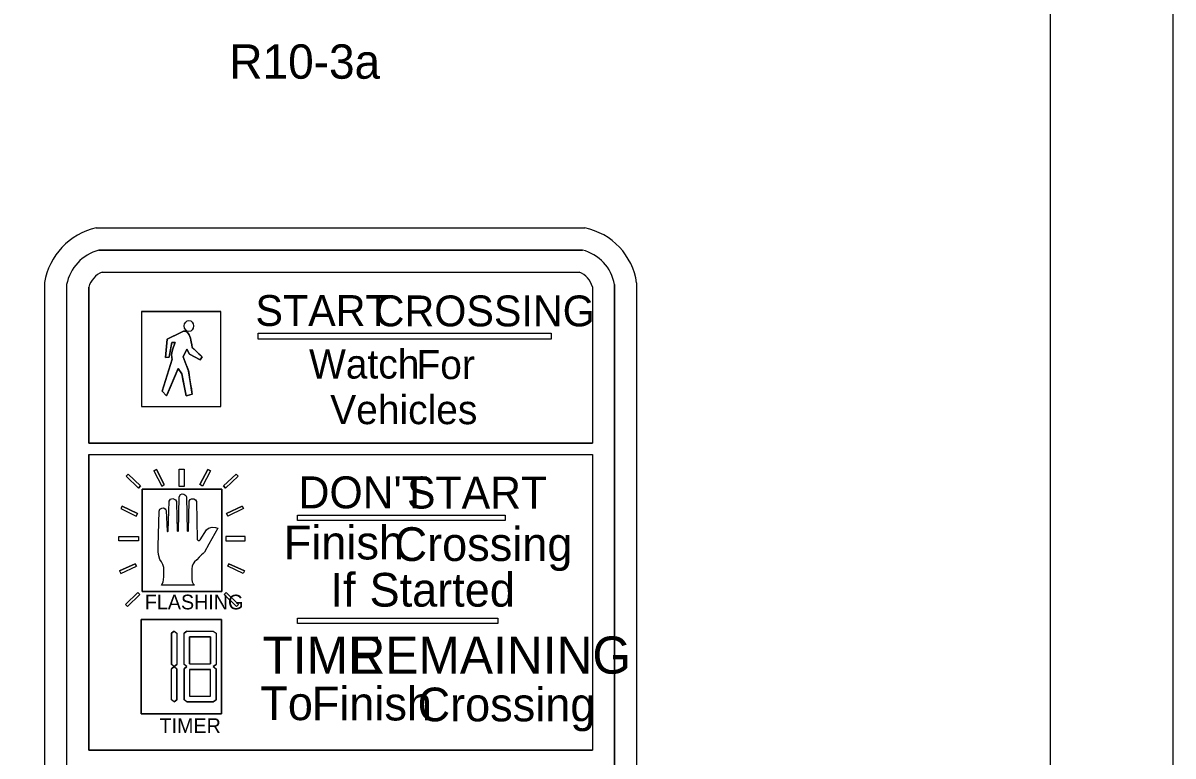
# Model space of a CAD drawing. Extents: x 1896459 to 1901611, y 1616229 to 1617416.
# Drawn here: x 1897924.9 to 1898159.1, y 1616969.5 to 1617118.8 of the extents above; entities that cross this region are included whole.
import ezdxf

# ---------------------------------------------------------------- set-up
doc = ezdxf.new("R2010")
doc.units = 0
for name, color, linetype in [('Level 8', 7, 'Continuous'), ('ROW_PR_Notes', 7, 'Continuous'), ('Sheets_General Details', 7, 'Continuous'), ('Signals_EX_Above Ground', 7, 'Continuous')]:
    doc.layers.add(name, color=color, linetype=linetype)

msp = doc.modelspace()

# ---------------------------------------------------------------- linework, layer by layer
at = {"layer": 'ROW_PR_Notes'}
for p, q in [((1897939.77, 1617077.06), (1898039.28, 1617077.06)), ((1897940.32, 1617072.56), (1898038.79, 1617072.56)), ((1898038.79, 1617072.56), (1897940.32, 1617072.56)), ((1897941.02, 1617068.06), (1898038.14, 1617068.06)), ((1897941.02, 1617068.06), (1898038.14, 1617068.06)), ((1897929.26, 1617065.93), (1897929.26, 1616886.19)), ((1897933.76, 1617065.54), (1897933.76, 1616886.41)), ((1897933.76, 1617065.54), (1897933.76, 1616886.41)), ((1897938.26, 1617065.02), (1897938.26, 1617033.2)), ((1897938.26, 1617033.2), (1897938.26, 1617065.02)), ((1898040.84, 1617065.07), (1898040.84, 1617033.2)), ((1898040.84, 1617065.07), (1898040.84, 1617033.2)), ((1898045.34, 1617065.54), (1898045.34, 1616886.41)), ((1898045.34, 1616886.41), (1898045.34, 1617065.54)), ((1898049.84, 1617065.89), (1898049.84, 1616886.08)), ((1897949, 1617060.03), (1897965.15, 1617060.03)), ((1897965.15, 1617060.03), (1897949, 1617060.03)), ((1897957.17, 1617055.86), (1897957.56, 1617056.04)), ((1897953.93, 1617050.65), (1897954.24, 1617054.42)), ((1897959.06, 1617054.21), (1897959.15, 1617053.85)), ((1897959.15, 1617053.85), (1897959.28, 1617053.23)), ((1897959.28, 1617053.23), (1897959.35, 1617052.74)), ((1897953.22, 1617043.83), (1897955.28, 1617050.34)), ((1897954.66, 1617050.73), (1897953.93, 1617050.65)), ((1897955.15, 1617051.24), (1897955.21, 1617051.65)), ((1897955.21, 1617051.65), (1897955.34, 1617052.22)), ((1897955.28, 1617050.34), (1897955.21, 1617050.62)), ((1897958.76, 1617051.34), (1897958.27, 1617052.39)), ((1897960.99, 1617050.19), (1897958.76, 1617051.34)), ((1897961.39, 1617050.84), (1897960.99, 1617050.19)), ((1897957.6, 1617045.39), (1897957.22, 1617047.33)), ((1897954.11, 1617042.89), (1897953.22, 1617043.83)), ((1897938.26, 1617033.2), (1898040.84, 1617033.2)), ((1898040.84, 1617033.2), (1897938.26, 1617033.2)), ((1897938.26, 1617030.88), (1898040.84, 1617030.88)), ((1897938.26, 1617030.88), (1897938.26, 1616970.64)), ((1897938.26, 1616970.64), (1897938.26, 1617030.88)), ((1897938.26, 1617030.88), (1898040.84, 1617030.88)), ((1898040.84, 1617030.88), (1898040.84, 1616970.64)), ((1898040.84, 1617030.88), (1898040.84, 1616970.64)), ((1897946.27, 1617026.91), (1897945.87, 1617026.48)), ((1897946.27, 1617026.91), (1897945.87, 1617026.48)), ((1897946.27, 1617026.91), (1897948.81, 1617024.5)), ((1897948.81, 1617024.5), (1897946.27, 1617026.91)), ((1897951.52, 1617027.6), (1897952.04, 1617027.87)), ((1897952.04, 1617027.87), (1897951.52, 1617027.6)), ((1897951.52, 1617027.6), (1897953.13, 1617024.49)), ((1897951.52, 1617027.6), (1897953.13, 1617024.49)), ((1897952.04, 1617027.87), (1897953.66, 1617024.77)), ((1897953.66, 1617024.77), (1897952.04, 1617027.87)), ((1897962.5, 1617027.87), (1897960.89, 1617024.77)), ((1897960.89, 1617024.77), (1897962.5, 1617027.87)), ((1897963.03, 1617027.6), (1897961.41, 1617024.49)), ((1897963.03, 1617027.6), (1897961.41, 1617024.49)), ((1897963.03, 1617027.6), (1897962.5, 1617027.87)), ((1897962.5, 1617027.87), (1897963.03, 1617027.6)), ((1897968.27, 1617026.91), (1897965.73, 1617024.5)), ((1897965.73, 1617024.5), (1897968.27, 1617026.91)), ((1897968.27, 1617026.91), (1897968.68, 1617026.48)), ((1897968.27, 1617026.91), (1897968.68, 1617026.48)), ((1897945.87, 1617026.48), (1897948.41, 1617024.07)), ((1897945.87, 1617026.48), (1897948.41, 1617024.07)), ((1897948.81, 1617024.5), (1897948.41, 1617024.07)), ((1897948.41, 1617024.07), (1897948.81, 1617024.5)), ((1897953.13, 1617024.49), (1897953.66, 1617024.77)), ((1897953.13, 1617024.49), (1897953.66, 1617024.77)), ((1897961.41, 1617024.49), (1897960.89, 1617024.77)), ((1897961.41, 1617024.49), (1897960.89, 1617024.77)), ((1897965.73, 1617024.5), (1897966.14, 1617024.07)), ((1897966.14, 1617024.07), (1897965.73, 1617024.5)), ((1897968.68, 1617026.48), (1897966.14, 1617024.07)), ((1897968.68, 1617026.48), (1897966.14, 1617024.07)), ((1897945.05, 1617020.41), (1897944.79, 1617019.88)), ((1897945.05, 1617020.41), (1897944.79, 1617019.88)), ((1897944.79, 1617019.88), (1897947.95, 1617018.37)), ((1897944.79, 1617019.88), (1897947.95, 1617018.37)), ((1897945.05, 1617020.41), (1897948.2, 1617018.9)), ((1897948.2, 1617018.9), (1897945.05, 1617020.41)), ((1897969.5, 1617020.41), (1897966.34, 1617018.9)), ((1897966.34, 1617018.9), (1897969.5, 1617020.41)), ((1897969.76, 1617019.88), (1897966.6, 1617018.37)), ((1897969.76, 1617019.88), (1897966.6, 1617018.37)), ((1897969.5, 1617020.41), (1897969.76, 1617019.88)), ((1897969.5, 1617020.41), (1897969.76, 1617019.88)), ((1897948.2, 1617018.9), (1897947.95, 1617018.37)), ((1897947.95, 1617018.37), (1897948.2, 1617018.9)), ((1897966.34, 1617018.9), (1897966.6, 1617018.37)), ((1897966.6, 1617018.37), (1897966.34, 1617018.9)), ((1897944.56, 1617007.19), (1897947.73, 1617008.66)), ((1897947.73, 1617008.66), (1897944.56, 1617007.19)), ((1897944.81, 1617006.66), (1897947.98, 1617008.13)), ((1897944.81, 1617006.66), (1897947.98, 1617008.13)), ((1897947.73, 1617008.66), (1897947.98, 1617008.13)), ((1897947.98, 1617008.13), (1897947.73, 1617008.66)), ((1897966.81, 1617008.66), (1897966.56, 1617008.13)), ((1897966.56, 1617008.13), (1897966.81, 1617008.66)), ((1897969.74, 1617006.66), (1897966.56, 1617008.13)), ((1897969.74, 1617006.66), (1897966.56, 1617008.13)), ((1897969.99, 1617007.19), (1897966.81, 1617008.66)), ((1897966.81, 1617008.66), (1897969.99, 1617007.19)), ((1897944.56, 1617007.19), (1897944.81, 1617006.66)), ((1897944.56, 1617007.19), (1897944.81, 1617006.66)), ((1897969.99, 1617007.19), (1897969.74, 1617006.66)), ((1897969.99, 1617007.19), (1897969.74, 1617006.66)), ((1897959.71, 1617004.32), (1897959.72, 1617004.33)), ((1897959.72, 1617004.33), (1897959.71, 1617004.32)), ((1897945.78, 1617000.36), (1897948.28, 1617002.8)), ((1897948.28, 1617002.8), (1897945.78, 1617000.36)), ((1897946.19, 1616999.93), (1897948.69, 1617002.38)), ((1897946.19, 1616999.93), (1897948.69, 1617002.38)), ((1897948.28, 1617002.8), (1897948.69, 1617002.38)), ((1897948.69, 1617002.38), (1897948.28, 1617002.8)), ((1897966.27, 1617002.8), (1897965.86, 1617002.38)), ((1897965.86, 1617002.38), (1897966.27, 1617002.8)), ((1897968.36, 1616999.93), (1897965.86, 1617002.38)), ((1897968.36, 1616999.93), (1897965.86, 1617002.38)), ((1897968.77, 1617000.36), (1897966.27, 1617002.8)), ((1897966.27, 1617002.8), (1897968.77, 1617000.36)), ((1897945.78, 1617000.36), (1897946.19, 1616999.93)), ((1897945.78, 1617000.36), (1897946.19, 1616999.93)), ((1897968.77, 1617000.36), (1897968.36, 1616999.93)), ((1897968.77, 1617000.36), (1897968.36, 1616999.93)), ((1897955.67, 1616994.9), (1897955.09, 1616994.48)), ((1897955.09, 1616994.48), (1897955.67, 1616994.9)), ((1897955.09, 1616994.48), (1897955.09, 1616988.12)), ((1897955.09, 1616988.12), (1897955.09, 1616994.48)), ((1897955.67, 1616994.9), (1897956.24, 1616994.48)), ((1897955.67, 1616994.9), (1897956.24, 1616994.48)), ((1897956.24, 1616994.48), (1897956.24, 1616988.12)), ((1897956.24, 1616994.48), (1897956.24, 1616988.12)), ((1897958.25, 1616994.9), (1897957.67, 1616994.48)), ((1897957.67, 1616994.48), (1897958.25, 1616994.9)), ((1897957.67, 1616988.12), (1897957.67, 1616994.48)), ((1897957.67, 1616988.12), (1897957.67, 1616994.48)), ((1897958.25, 1616994.9), (1897963.62, 1616994.9)), ((1897958.25, 1616994.9), (1897963.62, 1616994.9)), ((1897963.62, 1616994.9), (1897964.2, 1616994.48)), ((1897963.62, 1616994.9), (1897964.2, 1616994.48)), ((1897964.2, 1616994.48), (1897964.2, 1616988.12)), ((1897964.2, 1616994.48), (1897964.2, 1616988.12)), ((1897958.82, 1616993.75), (1897963.05, 1616993.75)), ((1897958.82, 1616988.28), (1897958.82, 1616993.75)), ((1897963.05, 1616993.75), (1897958.82, 1616993.75)), ((1897958.82, 1616993.75), (1897958.82, 1616988.28)), ((1897963.05, 1616993.75), (1897963.05, 1616988.28)), ((1897963.05, 1616988.28), (1897963.05, 1616993.75)), ((1897955.67, 1616987.7), (1897955.09, 1616988.12)), ((1897955.67, 1616987.7), (1897955.09, 1616988.12)), ((1897955.67, 1616987.7), (1897955.09, 1616987.27)), ((1897955.09, 1616987.27), (1897955.67, 1616987.7)), ((1897955.09, 1616980.92), (1897955.09, 1616987.27)), ((1897955.09, 1616980.92), (1897955.09, 1616987.27)), ((1897955.67, 1616987.7), (1897956.24, 1616988.12)), ((1897956.24, 1616988.12), (1897955.67, 1616987.7)), ((1897955.67, 1616987.7), (1897956.24, 1616987.27)), ((1897955.67, 1616987.7), (1897956.24, 1616987.27)), ((1897956.24, 1616980.92), (1897956.24, 1616987.27)), ((1897956.24, 1616987.27), (1897956.24, 1616980.92)), ((1897958.25, 1616987.7), (1897957.67, 1616988.12)), ((1897958.25, 1616987.7), (1897957.67, 1616988.12)), ((1897958.25, 1616987.7), (1897957.67, 1616987.27)), ((1897958.25, 1616987.7), (1897957.67, 1616987.27)), ((1897957.67, 1616987.27), (1897958.25, 1616987.7)), ((1897957.67, 1616987.27), (1897957.67, 1616980.92)), ((1897957.67, 1616980.92), (1897957.67, 1616987.27)), ((1897958.82, 1616988.28), (1897963.05, 1616988.28)), ((1897958.82, 1616988.28), (1897963.05, 1616988.28)), ((1897958.82, 1616987.11), (1897958.82, 1616981.64)), ((1897958.82, 1616987.11), (1897963.05, 1616987.11)), ((1897958.82, 1616987.11), (1897958.82, 1616981.64)), ((1897963.05, 1616987.11), (1897958.82, 1616987.11)), ((1897963.05, 1616981.64), (1897963.05, 1616987.11)), ((1897963.05, 1616981.64), (1897963.05, 1616987.11)), ((1897963.62, 1616987.7), (1897964.2, 1616988.12)), ((1897964.2, 1616988.12), (1897963.62, 1616987.7)), ((1897963.62, 1616987.7), (1897964.2, 1616987.27)), ((1897963.62, 1616987.7), (1897964.2, 1616987.27)), ((1897963.62, 1616987.7), (1897964.2, 1616987.27)), ((1897964.2, 1616980.92), (1897964.2, 1616987.27)), ((1897964.2, 1616987.27), (1897964.2, 1616980.92)), ((1897955.67, 1616980.49), (1897955.09, 1616980.92)), ((1897955.67, 1616980.49), (1897955.09, 1616980.92)), ((1897955.67, 1616980.49), (1897956.24, 1616980.92)), ((1897956.24, 1616980.92), (1897955.67, 1616980.49)), ((1897958.25, 1616980.49), (1897957.67, 1616980.92)), ((1897958.25, 1616980.49), (1897957.67, 1616980.92)), ((1897958.25, 1616980.49), (1897963.62, 1616980.49)), ((1897963.62, 1616980.49), (1897958.25, 1616980.49)), ((1897958.82, 1616981.64), (1897963.05, 1616981.64)), ((1897958.82, 1616981.64), (1897963.05, 1616981.64)), ((1897963.62, 1616980.49), (1897964.2, 1616980.92)), ((1897964.2, 1616980.92), (1897963.62, 1616980.49)), ((1897938.26, 1616970.64), (1898040.84, 1616970.64)), ((1898040.84, 1616970.64), (1897938.26, 1616970.64))]:
    msp.add_line(p, q, dxfattribs=at)
for points in [[(1897949, 1617060.03), (1897949, 1617040.71), (1897965.15, 1617040.71), (1897965.15, 1617060.03)], [(1897949, 1617060.03), (1897949, 1617040.71), (1897965.15, 1617040.71), (1897965.15, 1617060.03)], [(1897954.24, 1617054.42), (1897955.59, 1617055.09), (1897957.17, 1617055.86)], [(1897957.56, 1617056.04), (1897957.94, 1617056.04), (1897958.14, 1617055.98)], [(1897958.14, 1617055.98), (1897958.33, 1617055.86), (1897958.46, 1617055.7), (1897958.7, 1617055.32), (1897958.87, 1617054.93), (1897958.96, 1617054.59), (1897959.06, 1617054.21)], [(1897955.34, 1617052.22), (1897955.53, 1617052.82), (1897955.74, 1617053.4), (1897955.88, 1617053.75), (1897955.18, 1617053.74), (1897955.01, 1617052.74), (1897954.93, 1617052.3)], [(1897959.35, 1617052.74), (1897960.02, 1617052.12), (1897961.39, 1617050.84)], [(1897954.93, 1617052.3), (1897954.81, 1617051.54), (1897954.66, 1617050.73)], [(1897955.21, 1617050.62), (1897955.16, 1617051.01), (1897955.15, 1617051.24)], [(1897958.27, 1617052.39), (1897957.9, 1617051.63), (1897957.49, 1617050.8), (1897957.69, 1617050.28), (1897958.13, 1617049.17), (1897958.59, 1617047.98)], [(1897957.22, 1617047.33), (1897956.5, 1617048.4), (1897956.01, 1617047.25), (1897954.22, 1617043.11), (1897954.11, 1617042.89)], [(1897958.59, 1617047.98), (1897958.61, 1617047.88), (1897958.62, 1617047.8)], [(1897958.62, 1617047.8), (1897958.65, 1617047.62), (1897958.71, 1617047.22)], [(1897958.71, 1617047.22), (1897958.72, 1617047.17), (1897958.82, 1617046.54), (1897959.01, 1617045.27), (1897959.17, 1617044.3), (1897959.28, 1617043.61), (1897959.34, 1617043.19), (1897958.62, 1617043), (1897958.1, 1617042.89), (1897957.89, 1617043.89), (1897957.7, 1617044.87), (1897957.6, 1617045.39)], [(1897949.15, 1617003), (1897965.4, 1617003), (1897965.4, 1617023.84), (1897949.15, 1617023.84), (1897949.15, 1617003)], [(1897959.71, 1617004.32), (1897953.09, 1617004.32), (1897953.42, 1617004.89), (1897953.55, 1617006), (1897953.56, 1617007.12), (1897953.54, 1617007.88), (1897953.37, 1617008.48), (1897953.06, 1617009.06), (1897952.75, 1617009.55), (1897952.48, 1617010.52), (1897952.42, 1617011.14), (1897952.43, 1617012.26), (1897952.59, 1617019.39), (1897952.75, 1617019.79), (1897953.13, 1617019.99), (1897953.48, 1617020.01), (1897953.82, 1617019.82), (1897953.99, 1617019.61), (1897954.01, 1617019.5), (1897954.22, 1617015.31), (1897954.29, 1617015.21), (1897954.35, 1617015.24), (1897954.47, 1617015.29), (1897954.65, 1617021.41), (1897954.91, 1617021.81), (1897955.42, 1617021.96), (1897955.94, 1617021.69), (1897956.12, 1617021.36), (1897956.14, 1617021.07), (1897956.26, 1617015.35), (1897956.38, 1617015.23), (1897956.52, 1617015.33), (1897956.68, 1617022.3), (1897956.98, 1617022.75), (1897957.28, 1617022.88), (1897957.66, 1617022.84), (1897958.01, 1617022.58), (1897958.16, 1617022.26), (1897958.3, 1617015.33), (1897958.42, 1617015.24), (1897958.55, 1617015.36), (1897958.69, 1617021.37), (1897958.91, 1617021.73), (1897959.21, 1617021.89), (1897959.68, 1617021.91), (1897960.03, 1617021.64), (1897960.18, 1617021.32), (1897960.25, 1617017.56), (1897960.37, 1617013.6), (1897960.54, 1617013.39), (1897960.79, 1617013.37), (1897960.98, 1617013.52), (1897962.24, 1617015.55), (1897962.67, 1617015.87), (1897963.43, 1617016.09), (1897964.09, 1617016.07), (1897964.54, 1617015.87), (1897962.71, 1617012.62), (1897961.81, 1617011.04), (1897961.56, 1617010.76), (1897961.25, 1617010.45), (1897960.76, 1617009.98), (1897960.25, 1617009.43), (1897959.83, 1617009.03), (1897959.51, 1617008.62), (1897959.32, 1617008.19), (1897959.27, 1617007.64), (1897959.28, 1617005.45), (1897959.36, 1617004.96), (1897959.54, 1617004.54), (1897959.72, 1617004.33)], [(1897948.94, 1616978.06), (1897965.32, 1616978.06), (1897965.32, 1616997.3), (1897948.94, 1616997.3), (1897948.94, 1616978.06)]]:
    msp.add_lwpolyline(points, dxfattribs=at)
for points in [[(1897953.93, 1617050.65), (1897954.66, 1617050.73), (1897955.18, 1617053.74), (1897955.88, 1617053.75), (1897955.53, 1617052.82), (1897955.34, 1617052.22), (1897955.21, 1617051.65), (1897955.15, 1617051.24), (1897955.21, 1617050.62), (1897955.28, 1617050.34), (1897953.22, 1617043.83), (1897954.11, 1617042.89), (1897956.5, 1617048.4), (1897957.22, 1617047.33), (1897958.1, 1617042.89), (1897959.34, 1617043.19), (1897958.59, 1617047.98), (1897957.49, 1617050.8), (1897958.27, 1617052.39), (1897958.76, 1617051.34), (1897960.99, 1617050.19), (1897961.39, 1617050.84), (1897959.35, 1617052.74), (1897959.28, 1617053.23), (1897959.15, 1617053.85), (1897959.06, 1617054.21), (1897958.96, 1617054.59), (1897958.87, 1617054.93), (1897958.7, 1617055.32), (1897958.46, 1617055.7), (1897958.33, 1617055.86), (1897958.14, 1617055.98), (1897957.94, 1617056.04), (1897957.56, 1617056.04), (1897957.17, 1617055.86), (1897954.24, 1617054.42)], [(1897972.78, 1617055.61), (1898032.45, 1617055.61), (1898032.45, 1617054.41), (1897972.78, 1617054.41)], [(1897956.68, 1617027.92), (1897957.67, 1617027.92), (1897957.67, 1617024.36), (1897956.68, 1617024.36)], [(1897949.15, 1617023.84), (1897965.4, 1617023.84), (1897965.4, 1617003), (1897949.15, 1617003)], [(1897980.77, 1617018.52), (1898023.06, 1617018.52), (1898023.06, 1617017.48), (1897980.77, 1617017.48)], [(1897944.4, 1617014.23), (1897948.39, 1617014.23), (1897948.39, 1617013.31), (1897944.4, 1617013.31)], [(1897970.15, 1617014.23), (1897966.16, 1617014.23), (1897966.16, 1617013.31), (1897970.15, 1617013.31)], [(1897948.94, 1616997.3), (1897965.32, 1616997.3), (1897965.32, 1616978.06), (1897948.94, 1616978.06)], [(1897980.77, 1616997.57), (1898021.58, 1616997.57), (1898021.58, 1616996.51), (1897980.77, 1616996.51)]]:
    msp.add_lwpolyline(points, close=True, dxfattribs=at)
for centre, radius, start, end in [((1897942.72, 1617063.75), 13.63, 102.4886, 170.7892), ((1898036.66, 1617064.01), 13.31, 8.0947, 78.6459), ((1897942.72, 1617063.75), 9.13, 105.2733, 168.7404), ((1897942.72, 1617063.75), 9.13, 105.2733, 168.7404), ((1898036.66, 1617064.01), 8.81, 9.9538, 76.0324), ((1898036.66, 1617064.01), 8.81, 9.9538, 76.0324), ((1897942.72, 1617063.75), 4.63, 111.5077, 164.1656), ((1897942.72, 1617063.75), 4.63, 111.5077, 164.1656), ((1898036.66, 1617064.01), 4.31, 14.2501, 69.9779), ((1898036.66, 1617064.01), 4.31, 14.2501, 69.9779)]:
    msp.add_arc(centre, radius, start, end, dxfattribs=at)
msp.add_ellipse((1897958.68, 1617057.09), major_axis=(0, -1.14), ratio=0.8364, dxfattribs=at)
at = {"layer": 'Sheets_General Details'}
msp.add_line((1898159.07, 1616316.47), (1898159.07, 1617416.47), dxfattribs=at)
for points in [[(1896459.07, 1616316.47), (1898159.07, 1616316.47), (1898159.07, 1617416.47), (1896459.07, 1617416.47)], [(1896559.07, 1617391.47), (1898134.07, 1617391.47), (1898134.07, 1616341.47), (1896559.07, 1616341.47)], [(1896559.07, 1617391.46), (1898134.07, 1617391.46), (1898134.07, 1616391.47), (1896559.07, 1616391.47)]]:
    msp.add_lwpolyline(points, close=True, dxfattribs=at)
at = {"layer": 'Signals_EX_Above Ground'}
for points in [[(1897954.24, 1617054.43), (1897956.77, 1617055.66), (1897957.17, 1617055.86), (1897957.56, 1617056.04), (1897957.94, 1617056.04), (1897958.14, 1617055.98), (1897958.33, 1617055.86), (1897958.46, 1617055.7), (1897958.7, 1617055.32), (1897958.87, 1617054.93), (1897958.96, 1617054.59), (1897959.06, 1617054.21), (1897959.15, 1617053.85), (1897959.28, 1617053.23), (1897959.35, 1617052.74), (1897959.58, 1617052.51), (1897960.01, 1617052.12), (1897960.38, 1617051.77), (1897960.72, 1617051.45), (1897961.12, 1617051.09), (1897961.39, 1617050.84), (1897960.99, 1617050.19), (1897958.76, 1617051.34), (1897958.27, 1617052.39), (1897957.89, 1617051.63), (1897957.49, 1617050.8), (1897957.69, 1617050.27), (1897957.91, 1617049.7), (1897958.12, 1617049.17), (1897958.29, 1617048.72), (1897958.42, 1617048.39), (1897958.59, 1617047.98), (1897958.61, 1617047.88), (1897958.64, 1617047.62), (1897958.72, 1617047.17), (1897958.82, 1617046.54), (1897959.01, 1617045.27), (1897959.17, 1617044.3), (1897959.28, 1617043.61), (1897959.34, 1617043.19), (1897958.62, 1617043), (1897958.1, 1617042.89), (1897957.89, 1617043.89), (1897957.7, 1617044.87), (1897957.45, 1617046.18), (1897957.29, 1617047.01), (1897957.22, 1617047.33), (1897956.5, 1617048.4), (1897956.01, 1617047.25), (1897954.22, 1617043.11), (1897954.11, 1617042.89), (1897953.22, 1617043.83), (1897955.28, 1617050.34), (1897955.21, 1617050.62), (1897955.16, 1617051.01), (1897955.15, 1617051.24), (1897955.21, 1617051.65), (1897955.34, 1617052.22), (1897955.53, 1617052.82), (1897955.75, 1617053.4), (1897955.88, 1617053.75), (1897955.18, 1617053.74), (1897955, 1617052.74), (1897954.81, 1617051.54), (1897954.66, 1617050.73), (1897953.93, 1617050.65), (1897954.24, 1617054.42)], [(1897959.71, 1617004.32), (1897953.09, 1617004.32), (1897953.42, 1617004.89), (1897953.55, 1617006), (1897953.56, 1617007.12), (1897953.54, 1617007.88), (1897953.37, 1617008.48), (1897953.06, 1617009.06), (1897952.75, 1617009.55), (1897952.48, 1617010.52), (1897952.42, 1617011.14), (1897952.43, 1617012.26), (1897952.59, 1617019.39), (1897952.75, 1617019.79), (1897953.13, 1617019.99), (1897953.48, 1617020.01), (1897953.82, 1617019.82), (1897953.99, 1617019.61), (1897954.01, 1617019.5), (1897954.22, 1617015.31), (1897954.29, 1617015.21), (1897954.35, 1617015.24), (1897954.47, 1617015.29), (1897954.65, 1617021.41), (1897954.91, 1617021.81), (1897955.42, 1617021.96), (1897955.94, 1617021.69), (1897956.12, 1617021.36), (1897956.14, 1617021.07), (1897956.26, 1617015.35), (1897956.38, 1617015.23), (1897956.52, 1617015.33), (1897956.68, 1617022.3), (1897956.98, 1617022.75), (1897957.28, 1617022.88), (1897957.66, 1617022.84), (1897958.01, 1617022.58), (1897958.16, 1617022.26), (1897958.3, 1617015.33), (1897958.42, 1617015.24), (1897958.55, 1617015.36), (1897958.69, 1617021.37), (1897958.91, 1617021.73), (1897959.21, 1617021.89), (1897959.68, 1617021.91), (1897960.03, 1617021.64), (1897960.18, 1617021.32), (1897960.25, 1617017.56), (1897960.37, 1617013.6), (1897960.54, 1617013.39), (1897960.79, 1617013.37), (1897960.98, 1617013.52), (1897962.24, 1617015.55), (1897962.67, 1617015.87), (1897963.43, 1617016.09), (1897964.09, 1617016.07), (1897964.54, 1617015.87), (1897962.71, 1617012.62), (1897961.81, 1617011.04), (1897961.56, 1617010.76), (1897961.25, 1617010.45), (1897960.76, 1617009.98), (1897960.25, 1617009.43), (1897959.83, 1617009.03), (1897959.51, 1617008.62), (1897959.32, 1617008.19), (1897959.27, 1617007.64), (1897959.28, 1617005.45), (1897959.36, 1617004.96), (1897959.54, 1617004.54), (1897959.72, 1617004.33)]]:
    msp.add_lwpolyline(points, dxfattribs=at)
msp.add_ellipse((1897958.68, 1617057.09), major_axis=(0, -1.14), ratio=0.8364, dxfattribs=at)

# ---------------------------------------------------------------- texts
at = {"layer": 'Level 8'}
msp.add_text('R10-3a', height=7, dxfattribs=at).set_placement((1897966.91, 1617107.47))
at = {"layer": 'ROW_PR_Notes'}
for s, height, p in [('START', 6.284, (1897972.22, 1617057.1)), ('CROSSING', 6.284, (1897996.5, 1617057.02)), ('Watch', 5.929, (1897983.14, 1617046.38)), ('For', 5.929, (1898005, 1617046.27)), ('Vehicles', 5.929, (1897987.44, 1617037.09)), ("DON'T", 6.509, (1897981, 1617019.94)), ('START', 6.509, (1898003.08, 1617019.9)), ('Finish', 6.863, (1897977.99, 1617009.53)), ('Crossing', 6.863, (1898000.55, 1617009.22)), ('If', 6.863, (1897987.48, 1616999.92)), ('Started', 6.863, (1897995.46, 1616999.92)), ('FLASHING', 3.001, (1897949.69, 1616999.35)), ('REMAINING', 7.569, (1897991.35, 1616986.26)), ('TIME', 7.569, (1897973.65, 1616986.26)), ('To', 6.863, (1897973.21, 1616976.79)), ('Finish', 6.863, (1897983.69, 1616976.73)), ('Crossing', 6.863, (1898005.23, 1616976.55)), ('TIMER', 3.001, (1897952.68, 1616974.16))]:
    msp.add_text(s, height=height, dxfattribs=at).set_placement(p)

doc.saveas('drawing.dxf')
